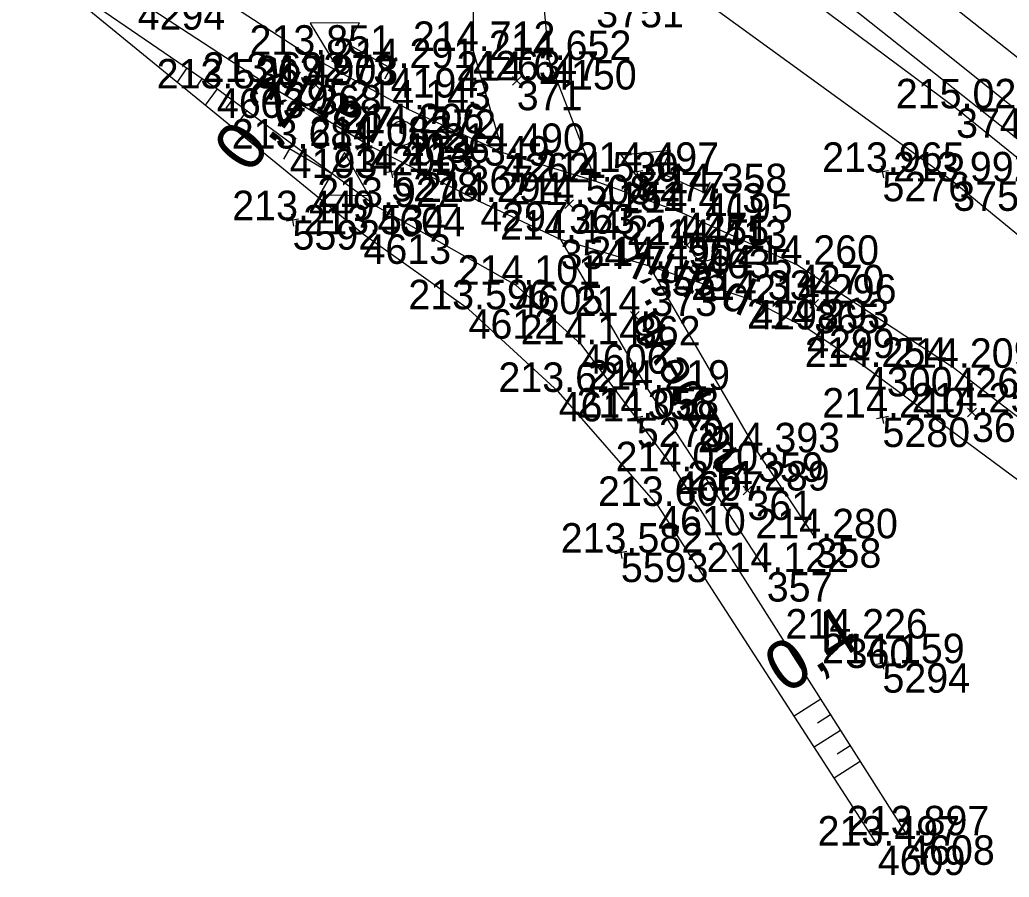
# Model space of a CAD drawing. Extents: x -556590 to -554855, y -1137918 to -1135717.
# Drawn here: x -556025.13 to -555984.84, y -1136128.71 to -1136093.81 of the extents above; entities that cross this region are included whole.
import ezdxf

# ---------------------------------------------------------------- set-up
doc = ezdxf.new("R2010")
doc.units = 0
for name, color, linetype in [('Vrstva 1', 7, 'Continuous'), ('Vrstva 4', 7, 'Continuous'), ('Vrstva 48', 7, 'Continuous'), ('Vrstva 49', 7, 'Continuous'), ('Vrstva 50', 7, 'Continuous'), ('Vrstva 51', 7, 'Continuous'), ('Vrstva 60', 7, 'Continuous'), ('Vrstva 61', 7, 'Continuous')]:
    doc.layers.add(name, color=color, linetype=linetype)

msp = doc.modelspace()

# ---------------------------------------------------------------- linework, layer by layer
at = {"layer": 'Vrstva 1'}
msp.add_lwpolyline([(-555960.154, -1136115.276), (-555966.686, -1136109.789), (-555972.391, -1136105.07), (-555980.79, -1136098.271), (-555988.861, -1136091.894), (-555996.698, -1136085.814), (-556000.171, -1136083.173), (-556003.144, -1136080.927), (-556011.619, -1136074.635), (-556019.74, -1136068.744), (-556028.634, -1136062.449), (-556038.038, -1136055.957), (-556046.905, -1136049.988), (-556056.242, -1136043.855), (-556065.684, -1136037.797), (-556074.529, -1136032.231), (-556083.366, -1136026.759), (-556092.119, -1136021.415), (-556099.887, -1136016.72), (-556108.312, -1136011.656), (-556117.392, -1136006.238), (-556126.405, -1136000.873), (-556135.067, -1135995.727), (-556144.312, -1135990.237)], dxfattribs=at)
at = {"layer": 'Vrstva 4'}
for points in [[(-555925.853, -1136147.731), (-555938.437, -1136136.155), (-555958.032, -1136119.331), (-555976.097, -1136104.237), (-555996.323, -1136088.056), (-556000.411, -1136085.031)], [(-556000.411, -1136085.031), (-555999.706, -1136086.488), (-555996.42, -1136089.198), (-555976.318, -1136105.138), (-555958.017, -1136120.333), (-555938.821, -1136137.014), (-555926.527, -1136148.412)]]:
    msp.add_lwpolyline(points, dxfattribs=at)
at = {"layer": 'Vrstva 48'}
for p, q in [((-556018.32, -1136095.77), (-556018.717, -1136096.351)), ((-556017.701, -1136096.193), (-556017.917, -1136096.51)), ((-556017.082, -1136096.617), (-556017.574, -1136097.285)), ((-556016.478, -1136097.063), (-556016.736, -1136097.411)), ((-556015.875, -1136097.508), (-556016.411, -1136098.235)), ((-555992.514, -1136121.471), (-555993.595, -1136122.158)), ((-555992.111, -1136122.104), (-555992.65, -1136122.446)), ((-555991.709, -1136122.737), (-555992.78, -1136123.417)), ((-555991.307, -1136123.37), (-555991.84, -1136123.709)), ((-555990.905, -1136124.003), (-555991.965, -1136124.677))]:
    msp.add_line(p, q, dxfattribs=at)
at = {"layer": 'Vrstva 49'}
for p, q in [((-556013.242, -1136096.644), (-556012.888, -1136096.29)), ((-556012.888, -1136096.644), (-556013.242, -1136096.29)), ((-556005.068, -1136096.469), (-556004.714, -1136096.115)), ((-556004.714, -1136096.469), (-556005.068, -1136096.115)), ((-556007.073, -1136099.923), (-556006.719, -1136099.569)), ((-556006.719, -1136099.923), (-556007.073, -1136099.569)), ((-556009.754, -1136099.953), (-556010.246, -1136100.047)), ((-556010.047, -1136099.754), (-556009.953, -1136100.246)), ((-555999.754, -1136099.953), (-556000.246, -1136100.047)), ((-556000.047, -1136099.754), (-555999.953, -1136100.246)), ((-555989.754, -1136099.953), (-555990.246, -1136100.047)), ((-555990.047, -1136099.754), (-555989.953, -1136100.246)), ((-556002.933, -1136101.495), (-556002.579, -1136101.141)), ((-556002.579, -1136101.495), (-556002.933, -1136101.141)), ((-556013.775, -1136101.92), (-556014.267, -1136102.014)), ((-556014.068, -1136101.721), (-556013.974, -1136102.213)), ((-555998.136, -1136103.161), (-555997.782, -1136102.807)), ((-555997.782, -1136103.161), (-555998.136, -1136102.807)), ((-555992.952, -1136105.546), (-555992.598, -1136105.192)), ((-555992.598, -1136105.546), (-555992.952, -1136105.192)), ((-556000.259, -1136106.044), (-555999.905, -1136105.69)), ((-555999.905, -1136106.044), (-556000.259, -1136105.69)), ((-555986.53, -1136109.972), (-555986.176, -1136109.618)), ((-555986.176, -1136109.972), (-555986.53, -1136109.618)), ((-555999.754, -1136109.953), (-556000.246, -1136110.047)), ((-556000.047, -1136109.754), (-555999.953, -1136110.246)), ((-555989.754, -1136109.953), (-555990.246, -1136110.047)), ((-555990.047, -1136109.754), (-555989.953, -1136110.246)), ((-555995.672, -1136113.149), (-555995.318, -1136112.795)), ((-555995.318, -1136113.149), (-555995.672, -1136112.795)), ((-556000.699, -1136115.253), (-556000.605, -1136115.745)), ((-556000.406, -1136115.452), (-556000.898, -1136115.546)), ((-555991.674, -1136119.172), (-555991.32, -1136118.818)), ((-555991.32, -1136119.172), (-555991.674, -1136118.818)), ((-555989.754, -1136119.953), (-555990.246, -1136120.047)), ((-555990.047, -1136119.754), (-555989.953, -1136120.246))]:
    msp.add_line(p, q, dxfattribs=at)
for points in [[(-555927.093, -1136149.006), (-555938.231, -1136138.726), (-555956.655, -1136122.616), (-555972.751, -1136108.933), (-555987.001, -1136097.415), (-555999.041, -1136088.452), (-556000.587, -1136088.062), (-556001.298, -1136088.491), (-556001.983, -1136090.415), (-556001.654, -1136092.921)], [(-556025.124, -1136091.119), (-556017.1, -1136096.604), (-556010.566, -1136101.426), (-556004.939, -1136104.595), (-556002.279, -1136107.017), (-555998.413, -1136112.186), (-555988.996, -1136127.007)], [(-555990.188, -1136127.423), (-555999.135, -1136113.598), (-556003.186, -1136108.957), (-556006.853, -1136105.593), (-556011.132, -1136102.546), (-556025.124, -1136091.119)], [(-556001.654, -1136092.921), (-556000.619, -1136091.366), (-555999.97, -1136091.058), (-555987.117, -1136100.388), (-555969.313, -1136115.015), (-555950.367, -1136132.06), (-555929.266, -1136151.301)]]:
    msp.add_lwpolyline(points, dxfattribs=at)
at = {"layer": 'Vrstva 50'}
for p, q in [((-556009.608, -1136098.427), (-556009.508, -1136098.427)), ((-555997.281, -1136103.136), (-555997.181, -1136103.136))]:
    msp.add_line(p, q, dxfattribs=at)
for centre in [(-556009.558, -1136098.427), (-555997.231, -1136103.136)]:
    msp.add_circle(centre, 0.5, dxfattribs=at)
at = {"layer": 'Vrstva 51'}
for p, q in [((-556010.268, -1136096.212), (-556009.782, -1136095.338)), ((-556013.882, -1136098.621), (-556014.392, -1136099.481)), ((-555997.427, -1136101.324), (-555997.015, -1136100.414))]:
    msp.add_line(p, q, dxfattribs=at)
for points in [[(-556003.109, -1136102.758), (-556006.375, -1136101.225), (-556010.882, -1136098.948), (-556015.231, -1136096.337), (-556020.327, -1136093.013), (-556028.542, -1136087.117), (-556040.188, -1136079.041), (-556043.827, -1136076.734), (-556048.783, -1136074.01), (-556065.089, -1136065.628), (-556077.857, -1136058.711), (-556079.979, -1136057.374), (-556081.878, -1136055.64), (-556083.273, -1136053.979), (-556084.513, -1136051.523), (-556088.912, -1136041.262), (-556090.343, -1136038.92), (-556092.002, -1136037.117), (-556093.982, -1136035.652), (-556110.016, -1136025.492), (-556130.533, -1136012.591), (-556156.21, -1135997.017)], [(-555952.273, -1136137.241), (-555973.316, -1136118.908), (-555980.425, -1136113.088), (-555987.111, -1136107.976), (-555993.488, -1136103.784), (-555998.163, -1136101.664), (-556001.659, -1136100.399), (-556005.463, -1136099.23), (-556009.295, -1136097.462), (-556013.414, -1136095.232), (-556020.931, -1136090.347), (-556037.809, -1136078.372)], [(-556001.659, -1136100.399), (-556003.575, -1136095.449), (-556004.015, -1136090.639), (-556002.983, -1136087.053), (-556002.042, -1136085.799), (-556001.118, -1136084.872), (-556000.466, -1136083.993), (-556003.781, -1136081.476), (-556004.466, -1136082.481), (-556004.741, -1136083.38), (-556005.484, -1136085.672), (-556006.678, -1136090.117), (-556006.669, -1136095.077), (-556005.463, -1136099.23)], [(-556010.025, -1136095.775), (-556011.773, -1136094.804), (-556011.288, -1136093.93), (-556013.303, -1136093.954), (-556012.259, -1136095.678), (-556011.773, -1136094.804)], [(-556014.137, -1136099.051), (-556012.416, -1136100.069), (-556012.925, -1136100.93), (-556010.909, -1136100.96), (-556011.906, -1136099.209), (-556012.416, -1136100.069)], [(-555997.221, -1136100.869), (-555999.042, -1136100.043), (-555998.629, -1136099.132), (-556000.636, -1136099.32), (-555999.455, -1136100.954), (-555999.042, -1136100.043)], [(-556003.109, -1136102.758), (-555999.554, -1136108.866), (-555994.711, -1136116.291)], [(-555931.804, -1136158.582), (-555941.684, -1136149.382), (-555955.479, -1136137.107), (-555971.889, -1136122.69), (-555982.305, -1136114.162), (-555990.712, -1136107.939), (-555993.068, -1136106.378), (-555995.342, -1136105.215), (-555999.481, -1136103.835), (-556003.109, -1136102.758)], [(-555992.721, -1136114.916), (-555995.071, -1136111.416), (-555999.481, -1136103.835)]]:
    msp.add_lwpolyline(points, dxfattribs=at)
at = {"layer": 'Vrstva 60'}
for p, q in [((-556006.669, -1136095.077), (-556006.669, -1136095.077)), ((-556013.414, -1136095.232), (-556013.414, -1136095.232)), ((-556003.575, -1136095.449), (-556003.575, -1136095.449)), ((-556010.025, -1136095.775), (-556010.025, -1136095.775)), ((-556015.231, -1136096.337), (-556015.231, -1136096.337)), ((-556004.891, -1136096.292), (-556004.891, -1136096.292)), ((-556017.1, -1136096.604), (-556017.1, -1136096.604)), ((-556013.065, -1136096.467), (-556013.065, -1136096.467)), ((-556009.295, -1136097.462), (-556009.295, -1136097.462)), ((-555987.001, -1136097.415), (-555987.001, -1136097.415)), ((-556009.558, -1136098.427), (-556009.558, -1136098.427)), ((-556014.137, -1136099.051), (-556014.137, -1136099.051)), ((-556010.882, -1136098.948), (-556010.882, -1136098.948)), ((-556005.463, -1136099.23), (-556005.463, -1136099.23)), ((-556006.896, -1136099.746), (-556006.896, -1136099.746)), ((-556010, -1136100), (-556010, -1136100)), ((-556000, -1136100), (-556000, -1136100)), ((-555990, -1136100), (-555990, -1136100)), ((-555987.117, -1136100.388), (-555987.117, -1136100.388)), ((-556001.659, -1136100.399), (-556001.659, -1136100.399)), ((-555997.221, -1136100.869), (-555997.221, -1136100.869)), ((-556010.566, -1136101.426), (-556010.566, -1136101.426)), ((-556006.375, -1136101.225), (-556006.375, -1136101.225)), ((-556002.756, -1136101.318), (-556002.756, -1136101.318)), ((-556014.021, -1136101.967), (-556014.021, -1136101.967)), ((-555998.163, -1136101.664), (-555998.163, -1136101.664)), ((-556011.132, -1136102.546), (-556011.132, -1136102.546)), ((-556003.109, -1136102.758), (-556003.109, -1136102.758)), ((-555997.959, -1136102.984), (-555997.959, -1136102.984)), ((-555997.231, -1136103.136), (-555997.231, -1136103.136)), ((-555999.481, -1136103.835), (-555999.481, -1136103.835)), ((-555993.488, -1136103.784), (-555993.488, -1136103.784)), ((-556004.939, -1136104.595), (-556004.939, -1136104.595)), ((-555995.342, -1136105.215), (-555995.342, -1136105.215)), ((-556006.853, -1136105.593), (-556006.853, -1136105.593)), ((-555992.775, -1136105.369), (-555992.775, -1136105.369)), ((-556000.082, -1136105.867), (-556000.082, -1136105.867)), ((-555993.068, -1136106.378), (-555993.068, -1136106.378)), ((-556002.279, -1136107.017), (-556002.279, -1136107.017)), ((-555990.712, -1136107.939), (-555990.712, -1136107.939)), ((-555987.111, -1136107.976), (-555987.111, -1136107.976)), ((-556003.186, -1136108.957), (-556003.186, -1136108.957)), ((-555999.554, -1136108.866), (-555999.554, -1136108.866)), ((-556000, -1136110), (-556000, -1136110)), ((-555990, -1136110), (-555990, -1136110)), ((-555986.353, -1136109.795), (-555986.353, -1136109.795)), ((-555995.071, -1136111.416), (-555995.071, -1136111.416)), ((-555998.413, -1136112.186), (-555998.413, -1136112.186)), ((-555995.495, -1136112.972), (-555995.495, -1136112.972)), ((-555999.135, -1136113.598), (-555999.135, -1136113.598)), ((-555992.721, -1136114.916), (-555992.721, -1136114.916)), ((-556000.652, -1136115.499), (-556000.652, -1136115.499)), ((-555994.711, -1136116.291), (-555994.711, -1136116.291)), ((-555991.497, -1136118.995), (-555991.497, -1136118.995)), ((-555990, -1136120), (-555990, -1136120)), ((-555988.996, -1136127.007), (-555988.996, -1136127.007)), ((-555990.188, -1136127.423), (-555990.188, -1136127.423))]:
    msp.add_line(p, q, dxfattribs=at)

# ---------------------------------------------------------------- texts
at = {"layer": 'Vrstva 48'}
for s, rotation, p in [('0,2', 53.5732, (-556015.753, -1136100.14)), ('0,4', 32.4312, (-555993.953, -1136121.284))]:
    msp.add_text(s, height=2, rotation=rotation, dxfattribs=at).set_placement(p)
at = {"layer": 'Vrstva 50'}
for rotation, p in [(151.5692, (-556010.077, -1136097.89)), (155.6069, (-555995.186, -1136104.855))]:
    msp.add_text('patník', height=1.5, rotation=rotation, dxfattribs=at).set_placement(p)
at = {"layer": 'Vrstva 51'}
msp.add_text('nezpevn.', height=1.5, rotation=120.1873, dxfattribs=at).set_placement((-555995.479, -1136112.049))
at = {"layer": 'Vrstva 60'}
for s, p in [('4294', (-556020.327, -1136094.213)), ('3751', (-556001.654, -1136094.121)), ('4263', (-556006.669, -1136096.277)), ('4273', (-556013.414, -1136096.432)), ('4150', (-556003.575, -1136096.649)), ('4194', (-556010.025, -1136096.975)), ('4295', (-556015.231, -1136097.537)), ('371', (-556004.891, -1136097.492)), ('4603', (-556017.1, -1136097.804)), ('368', (-556013.065, -1136097.667)), ('4272', (-556009.295, -1136098.662)), ('3746', (-555987.001, -1136098.615)), ('4636', (-556009.558, -1136099.627)), ('4193', (-556014.137, -1136100.251)), ('4296', (-556010.882, -1136100.148)), ('4262', (-556005.463, -1136100.43)), ('5278', (-556010, -1136101.2)), ('367', (-556006.896, -1136100.946)), ('5277', (-556000, -1136101.2)), ('5276', (-555990, -1136101.2)), ('3754', (-555987.117, -1136101.588)), ('4151', (-556001.659, -1136101.599)), ('4195', (-555997.221, -1136102.069)), ('4604', (-556010.566, -1136102.626)), ('4297', (-556006.375, -1136102.425)), ('363', (-556002.756, -1136102.518)), ('5592', (-556014.021, -1136103.167)), ('4271', (-555998.163, -1136102.864)), ('4613', (-556011.132, -1136103.746)), ('354', (-556003.109, -1136103.958)), ('364', (-555997.959, -1136104.184)), ('4635', (-555997.231, -1136104.336)), ('355', (-555999.481, -1136105.035)), ('4270', (-555993.488, -1136104.984)), ('4605', (-556004.939, -1136105.795)), ('4298', (-555995.342, -1136106.415)), ('4612', (-556006.853, -1136106.793)), ('365', (-555992.775, -1136106.569)), ('362', (-556000.082, -1136107.067)), ('4299', (-555993.068, -1136107.578)), ('4606', (-556002.279, -1136108.217)), ('4300', (-555990.712, -1136109.139)), ('4269', (-555987.111, -1136109.176)), ('356', (-555999.554, -1136110.066)), ('4611', (-556003.186, -1136110.157)), ('5279', (-556000, -1136111.2)), ('5280', (-555990, -1136111.2)), ('366', (-555986.353, -1136110.995)), ('359', (-555995.071, -1136112.616)), ('4607', (-555998.413, -1136113.386)), ('361', (-555995.495, -1136114.172)), ('4610', (-555999.135, -1136114.798)), ('358', (-555992.721, -1136116.116)), ('5593', (-556000.652, -1136116.699)), ('357', (-555994.711, -1136117.491)), ('360', (-555991.497, -1136120.195)), ('5294', (-555990, -1136121.2)), ('4608', (-555988.996, -1136128.207)), ('4609', (-555990.188, -1136128.623))]:
    msp.add_text(s, height=1.2, dxfattribs=at).set_placement(p)
at = {"layer": 'Vrstva 61'}
for s, p in [('214.712', (-556009.117, -1136095.077)), ('213.851', (-556015.771, -1136095.232)), ('214.652', (-556006.023, -1136095.449)), ('214.291', (-556012.382, -1136095.775)), ('213.692', (-556017.679, -1136096.337)), ('214.647', (-556007.343, -1136096.292)), ('213.536', (-556019.552, -1136096.604)), ('213.908', (-556015.519, -1136096.467)), ('214.143', (-556011.747, -1136097.462)), ('215.028', (-555989.455, -1136097.415)), ('214.206', (-556012.01, -1136098.427)), ('213.681', (-556016.494, -1136099.051)), ('214.083', (-556013.334, -1136098.948)), ('214.490', (-556007.914, -1136099.23)), ('214.349', (-556009.35, -1136099.746)), ('214.113', (-556012.452, -1136100)), ('214.530', (-556004.11, -1136100.399)), ('214.497', (-556002.452, -1136100)), ('213.965', (-555992.456, -1136100)), ('213.992', (-555989.565, -1136100.388)), ('214.358', (-555999.675, -1136100.869)), ('213.922', (-556013.014, -1136101.426)), ('214.294', (-556008.826, -1136101.225)), ('214.508', (-556005.21, -1136101.318)), ('213.449', (-556016.475, -1136101.967)), ('214.473', (-556000.615, -1136101.664)), ('213.534', (-556013.583, -1136102.546)), ('214.445', (-556005.565, -1136102.758)), ('214.455', (-556000.415, -1136102.984)), ('214.413', (-555999.683, -1136103.136)), ('214.490', (-556001.932, -1136103.835)), ('214.260', (-555995.939, -1136103.784)), ('214.101', (-556007.296, -1136104.595)), ('214.334', (-555997.793, -1136105.215)), ('213.596', (-556009.305, -1136105.593)), ('214.296', (-555995.227, -1136105.369)), ('214.373', (-556002.534, -1136105.867)), ('214.293', (-555995.52, -1136106.378)), ('214.149', (-556004.733, -1136107.017)), ('214.254', (-555993.163, -1136107.939)), ('214.209', (-555989.565, -1136107.976)), ('213.624', (-556005.637, -1136108.957)), ('214.219', (-556002.008, -1136108.866)), ('214.058', (-556002.454, -1136110)), ('214.210', (-555992.451, -1136110)), ('214.250', (-555988.804, -1136109.795)), ('214.393', (-555997.523, -1136111.416)), ('214.020', (-556000.864, -1136112.186)), ('214.289', (-555997.949, -1136112.972)), ('213.602', (-556001.583, -1136113.598)), ('214.280', (-555995.172, -1136114.916)), ('213.582', (-556003.1, -1136115.499)), ('214.122', (-555997.159, -1136116.291)), ('214.226', (-555993.949, -1136118.995)), ('214.159', (-555992.454, -1136120)), ('213.897', (-555991.448, -1136127.007)), ('213.497', (-555992.64, -1136127.423))]:
    msp.add_text(s, height=1.2, dxfattribs=at).set_placement(p)

doc.saveas('drawing.dxf')
